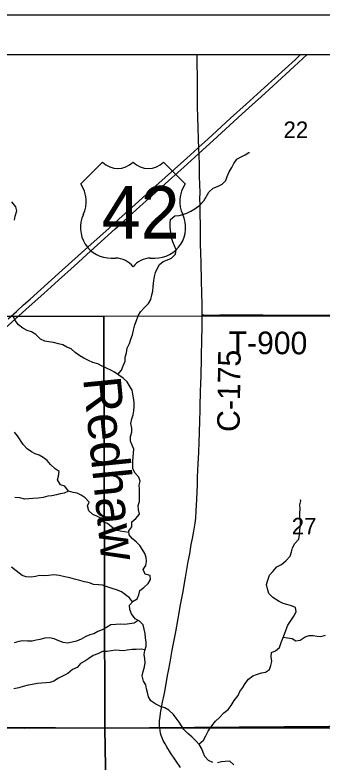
# Model space of a CAD drawing. Extents: x 0 to 34, y 0 to 22.
# Drawn here: x 14.264 to 15.039, y 14.196 to 16.078 of the extents above; entities that cross this region are included whole.
import ezdxf

# ---------------------------------------------------------------- set-up
doc = ezdxf.new("R2010")
doc.units = 0
for name, color, linetype in [('GM_X_County_Road', 7, 'Continuous'), ('GM_X_County_Road_Text', 7, 'Continuous'), ('GM_X_Minor_River', 7, 'Continuous'), ('GM_X_Minor_River_Text', 7, 'Continuous'), ('GM_X_Section', 7, 'Continuous'), ('GM_X_Section_Text', 7, 'Continuous'), ('GM_X_State_Route', 7, 'Continuous'), ('GM_X_Township_Road', 7, 'Continuous'), ('GM_X_Township_Road_Text', 7, 'Continuous'), ('GM_X_US_Location', 7, 'Continuous'), ('GM_X_US_Route', 7, 'Continuous'), ('GM_X_US_Shield', 7, 'Continuous'), ('SH_Data', 7, 'Continuous')]:
    doc.layers.add(name, color=color, linetype=linetype)

msp = doc.modelspace()

# ---------------------------------------------------------------- linework, layer by layer
at = {"layer": 'GM_X_County_Road'}
for points in [[(14.7287, 15.7292), (14.7285, 15.7359), (14.7281, 15.7443), (14.7274, 15.7607), (14.7262, 15.7973), (14.7256, 15.8164), (14.725, 15.8507), (14.7249, 15.8727), (14.7249, 15.9161), (14.7243, 15.9607), (14.7239, 15.9775)], [(14.7364, 15.3221), (14.7364, 15.3261), (14.7363, 15.3478), (14.7357, 15.3789), (14.7352, 15.4069), (14.7338, 15.4549), (14.7331, 15.4765), (14.7327, 15.5012), (14.7322, 15.5498), (14.7319, 15.5743), (14.7314, 15.5989), (14.731, 15.6143), (14.7311, 15.6304), (14.7302, 15.6707), (14.7297, 15.6956), (14.7287, 15.7292)], [(14.6297, 14.2821), (14.6292, 14.2856), (14.6289, 14.2916), (14.6293, 14.3006), (14.6302, 14.3098), (14.6316, 14.3191), (14.6368, 14.3466), (14.6404, 14.3649), (14.6438, 14.3832), (14.6494, 14.4137), (14.6517, 14.4259), (14.6556, 14.4478), (14.6612, 14.4781), (14.6698, 14.5239), (14.676, 14.5578), (14.6821, 14.5916), (14.6876, 14.6212), (14.6945, 14.661), (14.7016, 14.701), (14.705, 14.7202), (14.7091, 14.7438), (14.712, 14.7591), (14.7152, 14.7774), (14.7187, 14.798), (14.7202, 14.8102), (14.7217, 14.8287), (14.7229, 14.8574), (14.7244, 14.8947), (14.725, 14.9134), (14.7267, 14.9468), (14.7281, 14.9757), (14.7289, 15.0022), (14.7296, 15.0252), (14.7304, 15.056), (14.7311, 15.0813), (14.7317, 15.1026), (14.7323, 15.1187), (14.7327, 15.1321), (14.7333, 15.1468), (14.7341, 15.1708), (14.7344, 15.1832), (14.7347, 15.1987), (14.7349, 15.2205), (14.7357, 15.2578), (14.7362, 15.2919), (14.7364, 15.3221)], [(14.6816, 14.1823), (14.6568, 14.2195), (14.6476, 14.234), (14.6429, 14.2417), (14.6384, 14.2502), (14.6356, 14.2567), (14.6333, 14.2631), (14.6317, 14.2691), (14.6303, 14.2753), (14.6297, 14.2821)]]:
    msp.add_lwpolyline(points, dxfattribs=at)
at = {"layer": 'GM_X_Minor_River'}
for points in [[(14.5239, 15.1719), (14.5327, 15.1827), (14.5374, 15.1936), (14.542, 15.2053), (14.5425, 15.2159), (14.5456, 15.2265), (14.5472, 15.2383), (14.5534, 15.2504), (14.5565, 15.261), (14.5604, 15.2715), (14.5635, 15.284), (14.5667, 15.2973), (14.5709, 15.3082), (14.5748, 15.32), (14.5806, 15.3302), (14.5901, 15.3395), (14.6008, 15.3512), (14.607, 15.361), (14.6093, 15.3724), (14.6117, 15.3822), (14.6133, 15.394), (14.6142, 15.4084), (14.6162, 15.4186), (14.6189, 15.4288), (14.6235, 15.4394), (14.6285, 15.4492), (14.6384, 15.4563), (14.6491, 15.4611), (14.659, 15.4652), (14.6689, 15.475), (14.6709, 15.4856), (14.6668, 15.4962), (14.6623, 15.5062), (14.6587, 15.5187), (14.6572, 15.5297), (14.6558, 15.5419), (14.6555, 15.5529), (14.6564, 15.5624), (14.6678, 15.5714), (14.6781, 15.5724), (14.6879, 15.5746), (14.6978, 15.5786), (14.7081, 15.5835), (14.718, 15.5891), (14.7309, 15.5988), (14.7405, 15.609), (14.7535, 15.6316), (14.7642, 15.641), (14.7752, 15.6458), (14.787, 15.651), (14.7962, 15.6608), (14.7993, 15.6706), (14.8043, 15.6827), (14.8112, 15.6936), (14.8166, 15.7038), (14.8239, 15.7144), (14.8346, 15.72), (14.8448, 15.7252), (14.8544, 15.7315), (14.8559, 15.7315)], [(14.2629, 15.5605), (14.2649, 15.5707), (14.2688, 15.5843), (14.2666, 15.5946), (14.2561, 15.6065)], [(14.3395, 15.2562), (14.3285, 15.2609), (14.3165, 15.2728), (14.3056, 15.2793), (14.295, 15.2825), (14.2837, 15.2886), (14.2736, 15.2971), (14.2649, 15.3082), (14.2594, 15.3189)], [(14.6425, 14.3324), (14.6316, 14.3356), (14.6195, 14.3414), (14.6074, 14.3502), (14.6011, 14.3602), (14.5982, 14.3712), (14.5963, 14.3807), (14.5945, 14.3906), (14.5886, 14.4001), (14.5853, 14.4131), (14.5876, 14.4244), (14.5911, 14.4354), (14.5924, 14.4464), (14.5917, 14.4559), (14.5899, 14.4669), (14.5919, 14.4767), (14.595, 14.4877), (14.5951, 14.4976), (14.5936, 14.5086), (14.5926, 14.5196), (14.5904, 14.5303), (14.5875, 14.5413), (14.5781, 14.5509), (14.5679, 14.557), (14.5582, 14.5693), (14.5537, 14.5799), (14.5531, 14.5913), (14.5626, 14.6015), (14.5729, 14.6067), (14.5764, 14.6173), (14.5795, 14.6279), (14.589, 14.6358), (14.6001, 14.6455), (14.6063, 14.6561), (14.6056, 14.6656), (14.5927, 14.6695), (14.5879, 14.6809), (14.5941, 14.6911), (14.5957, 14.7013), (14.5954, 14.7112), (14.5917, 14.7215), (14.5853, 14.7318), (14.579, 14.7413), (14.5703, 14.7509), (14.5598, 14.7586), (14.5523, 14.7681), (14.5516, 14.778), (14.5589, 14.7886), (14.559, 14.8011), (14.5693, 14.8097), (14.5785, 14.8206), (14.5763, 14.8324), (14.5753, 14.8419), (14.5784, 14.8521), (14.5788, 14.862), (14.5782, 14.8734), (14.5783, 14.8832), (14.5776, 14.8931), (14.58, 14.9033), (14.577, 14.9132), (14.5676, 14.9236), (14.5617, 14.9342), (14.5618, 14.9547), (14.5623, 14.9642), (14.5631, 14.9748), (14.564, 14.9843), (14.5599, 14.9938), (14.5558, 15.0045), (14.5555, 15.0155), (14.559, 15.0268), (14.5588, 15.0371), (14.5562, 15.0489), (14.559, 15.0602), (14.5624, 15.0704), (14.5644, 15.0803), (14.5649, 15.0913), (14.565, 15.1011), (14.5636, 15.1133), (14.5618, 15.1228), (14.5596, 15.1323), (14.5528, 15.1438), (14.5472, 15.1537), (14.5375, 15.1629), (14.5262, 15.1702), (14.5157, 15.1783), (14.5058, 15.1833), (14.4949, 15.188), (14.4843, 15.193), (14.4734, 15.1988), (14.461, 15.2023), (14.45, 15.2074), (14.4383, 15.2128), (14.4282, 15.2193), (14.4161, 15.2278), (14.406, 15.237), (14.395, 15.2409), (14.3848, 15.2467), (14.3743, 15.2491), (14.3618, 15.2522), (14.3497, 15.2539), (14.3395, 15.2562)], [(14.5519, 14.7741), (14.5406, 14.7759), (14.5293, 14.7771), (14.5191, 14.7802), (14.5078, 14.7883), (14.498, 14.7964), (14.4882, 14.8003), (14.4807, 14.8098), (14.4705, 14.8152), (14.4603, 14.8195), (14.4506, 14.8283), (14.4476, 14.8409), (14.4511, 14.8507), (14.4414, 14.861), (14.4312, 14.8684), (14.4214, 14.873), (14.4108, 14.8746), (14.3991, 14.8785), (14.3898, 14.8904), (14.3792, 14.8943), (14.3713, 14.9065), (14.3741, 14.9163), (14.3757, 14.9277), (14.3655, 14.9346), (14.3539, 14.9454), (14.3456, 14.9553), (14.3358, 14.9634), (14.3257, 14.9688), (14.3155, 14.9723), (14.3057, 14.9773), (14.2948, 14.985), (14.285, 14.9957), (14.2708, 15.0175), (14.2633, 15.0271)], [(14.3991, 14.8785), (14.3888, 14.8729), (14.3786, 14.8711), (14.3691, 14.869), (14.357, 14.8664), (14.3468, 14.8654), (14.335, 14.8625), (14.3225, 14.8607), (14.3092, 14.8597), (14.299, 14.8586), (14.2888, 14.8584), (14.2763, 14.8611), (14.2638, 14.8624)], [(14.7284, 14.241), (14.7403, 14.2514), (14.7457, 14.2624), (14.7514, 14.2741), (14.7606, 14.2873), (14.7702, 14.2993), (14.7805, 14.308), (14.7916, 14.3196), (14.8019, 14.3282), (14.8095, 14.3384), (14.8176, 14.3512), (14.8276, 14.3633), (14.8318, 14.3739), (14.8391, 14.3837), (14.8449, 14.3935), (14.8533, 14.4044), (14.864, 14.413), (14.8735, 14.4167), (14.886, 14.4204), (14.8962, 14.4222), (14.9061, 14.4293), (14.91, 14.4395), (14.9124, 14.4493), (14.9109, 14.4611), (14.9114, 14.4721), (14.9217, 14.4758), (14.9316, 14.4848), (14.9355, 14.4969), (14.944, 14.5181), (14.9483, 14.5302), (14.9525, 14.5404), (14.9594, 14.551), (14.9675, 14.563), (14.974, 14.5747), (14.9718, 14.5854), (14.9616, 14.5893), (14.9503, 14.5928), (14.9405, 14.5952), (14.9307, 14.6002), (14.9149, 14.6102), (14.9051, 14.6205), (14.9014, 14.632), (14.8989, 14.6434), (14.9024, 14.6543), (14.9066, 14.6664), (14.9147, 14.6762), (14.925, 14.6875), (14.9368, 14.6931), (14.9475, 14.7028), (14.9589, 14.7149), (14.9616, 14.7251), (14.9644, 14.7357), (14.9702, 14.7463), (14.9801, 14.7572), (14.9825, 14.7693), (14.9826, 14.7807), (14.9849, 14.7905), (14.9843, 14.8026), (14.9832, 14.8125), (14.9833, 14.8231), (14.9838, 14.8334), (14.9831, 14.8436), (14.9858, 14.8535), (14.9847, 14.8561)], [(14.5607, 14.5995), (14.5532, 14.6099), (14.5434, 14.6168), (14.5333, 14.6249), (14.5227, 14.6292), (14.5095, 14.6331), (14.4993, 14.6366), (14.4853, 14.6413), (14.4747, 14.6422), (14.4626, 14.6431), (14.4521, 14.6473), (14.44, 14.6497), (14.4275, 14.6536), (14.4147, 14.6568), (14.4029, 14.6603), (14.3901, 14.6624), (14.3761, 14.6655), (14.3621, 14.6672), (14.3485, 14.6662), (14.3371, 14.6648), (14.3265, 14.666), (14.3159, 14.6631), (14.3049, 14.662), (14.2928, 14.6622), (14.2822, 14.6657), (14.2675, 14.6776), (14.2559, 14.6864)], [(14.575, 14.5528), (14.5648, 14.5461), (14.553, 14.5439), (14.5413, 14.5425), (14.5296, 14.543), (14.519, 14.5423), (14.5057, 14.5417), (14.495, 14.535), (14.484, 14.5286), (14.4737, 14.5249), (14.4631, 14.519), (14.4532, 14.5168), (14.4433, 14.512), (14.4315, 14.5056), (14.4194, 14.5008), (14.4084, 14.4975), (14.3966, 14.495), (14.3857, 14.497), (14.3747, 14.5016), (14.363, 14.5063), (14.3513, 14.5091), (14.3396, 14.508), (14.327, 14.5044), (14.3175, 14.5026), (14.3077, 14.5008), (14.2963, 14.5005), (14.2838, 14.501), (14.2743, 14.4992), (14.2626, 14.4959)], [(14.941, 14.5108), (14.9519, 14.5085), (14.9632, 14.5073), (14.973, 14.5015), (14.984, 14.5033), (14.9966, 14.5111), (15.0064, 14.5145), (15.0163, 14.5144), (15.0265, 14.5127), (15.0363, 14.5123), (15.0473, 14.5152)], [(14.5923, 14.4783), (14.5824, 14.4799), (14.5699, 14.4796), (14.5601, 14.4793), (14.5472, 14.4779), (14.5377, 14.4761), (14.5279, 14.4766), (14.518, 14.4778), (14.5067, 14.4761), (14.4972, 14.4743), (14.4854, 14.4747), (14.4736, 14.4688), (14.4615, 14.4644), (14.4504, 14.4565), (14.4402, 14.4498), (14.4299, 14.4442), (14.4215, 14.434), (14.4097, 14.4292), (14.3975, 14.4194), (14.3846, 14.4124), (14.3743, 14.4071), (14.3625, 14.4001), (14.3519, 14.3964), (14.342, 14.3953), (14.3314, 14.395), (14.3212, 14.394), (14.3079, 14.3915), (14.2973, 14.3893), (14.2847, 14.386), (14.2737, 14.3827), (14.2616, 14.3805)], [(14.7636, 14.1951), (14.7527, 14.2001), (14.7433, 14.2097), (14.7392, 14.22), (14.7355, 14.2295), (14.7299, 14.2394), (14.7202, 14.2497), (14.7108, 14.2593), (14.7007, 14.2681), (14.6901, 14.2777), (14.6845, 14.2873), (14.6782, 14.2968), (14.6711, 14.3064), (14.6643, 14.3159), (14.6523, 14.327), (14.6425, 14.3324)], [(14.8166, 14.1892), (14.8065, 14.198), (14.7947, 14.1978), (14.7852, 14.1967), (14.775, 14.1938)]]:
    msp.add_lwpolyline(points, dxfattribs=at)
at = {"layer": 'GM_X_Section'}
for points in [[(14.4882, 15.3186), (14.4911, 14.2816), (13.9911, 14.2848), (13.6079, 14.3123), (13.4623, 14.3061), (13.4573, 15.3188)], [(15.4934, 15.3198), (15.5087, 14.2889), (14.4911, 14.2816), (14.4882, 15.3186)], [(14.4911, 14.2816), (14.5077, 13.2997), (13.5746, 13.3006), (13.5034, 13.3022), (13.4623, 14.3061), (13.6079, 14.3123), (13.9911, 14.2848)], [(15.5087, 14.2889), (15.5148, 13.3016), (14.5623, 13.2983), (14.5077, 13.2997), (14.4911, 14.2816)]]:
    msp.add_lwpolyline(points, close=True, dxfattribs=at)
at = {"layer": 'GM_X_State_Route'}
msp.add_lwpolyline([(14.2231, 14.282), (14.2886, 14.2816), (14.3465, 14.2821), (14.4338, 14.2822), (14.4823, 14.2825), (14.5351, 14.2824), (14.5724, 14.2824), (14.6137, 14.2819), (14.6297, 14.2821), (14.6823, 14.2822), (14.7484, 14.2819), (14.7925, 14.2819), (14.8365, 14.2818), (14.8893, 14.282), (14.9483, 14.2821), (14.9949, 14.282), (15.0321, 14.2819), (15.0694, 14.282)], dxfattribs=at)
at = {"layer": 'GM_X_Township_Road'}
msp.add_lwpolyline([(14.7364, 15.3221), (14.7406, 15.322), (14.7561, 15.3218), (14.781, 15.322), (14.8338, 15.3222), (14.8587, 15.3222), (14.8898, 15.3219), (14.9333, 15.3218), (14.9644, 15.3216), (15.0546, 15.3215), (15.1012, 15.3213), (15.151, 15.3212), (15.1914, 15.321), (15.2349, 15.321), (15.2359, 15.321)], dxfattribs=at)
at = {"layer": 'GM_X_US_Route'}
for points in [[(14.2213, 15.2724), (14.2653, 15.3118), (14.2999, 15.343), (14.3369, 15.3763), (14.3737, 15.4098), (14.4132, 15.4447), (14.4453, 15.4742), (14.517, 15.5386), (14.5377, 15.5573), (14.5608, 15.5781), (14.5794, 15.5947), (14.6093, 15.6219), (14.6603, 15.6674), (14.6904, 15.6944), (14.7272, 15.7279), (14.7287, 15.7292), (14.7641, 15.7612), (14.8375, 15.8283), (14.8628, 15.8513), (14.886, 15.872), (14.9157, 15.8994), (14.9688, 15.9473), (15.0018, 15.9775)], [(14.2472, 15.3118), (14.2679, 15.3307), (14.2862, 15.3474), (14.3025, 15.3619), (14.3836, 15.4344), (14.4482, 15.4927), (14.5015, 15.5403), (14.5267, 15.5633), (14.5497, 15.5842), (14.6123, 15.6402), (14.6979, 15.717), (14.7255, 15.742), (14.7281, 15.7443), (14.7509, 15.7649), (14.7739, 15.7859), (14.8083, 15.8173), (14.8476, 15.8527), (14.8936, 15.8945), (14.9719, 15.9655), (14.985, 15.9775)]]:
    msp.add_lwpolyline(points, dxfattribs=at)
at = {"layer": 'GM_X_US_Shield'}
for p, q in [((14.4853, 15.7067), (14.4303, 15.6518)), ((14.694, 15.6518), (14.6391, 15.7067)), ((14.5072, 15.465), (14.5182, 15.465)), ((14.6061, 15.465), (14.6171, 15.465))]:
    msp.add_line(p, q, dxfattribs=at)
for centre, radius, start, end in [((14.5237, 15.7459), 0.0549, 225.573, 314.427), ((14.6006, 15.7459), 0.0549, 225.573, 314.427), ((14.3673, 15.6077), 0.0769, 334.5471, 35.0009), ((14.757, 15.6077), 0.0769, 144.9991, 205.4529), ((14.5064, 15.5419), 0.0769, 154.8319, 270.6383), ((14.618, 15.5419), 0.0769, 269.3617, 25.1681), ((14.5182, 15.4101), 0.0549, 36.8699, 90), ((14.6061, 15.4101), 0.0549, 90, 143.1301)]:
    msp.add_arc(centre, radius, start, end, dxfattribs=at)
at = {"layer": 'SH_Data'}
for p, q in [((9.0079, 16.0775), (16.0079, 16.0775)), ((9.1079, 15.9775), (15.9079, 15.9775))]:
    msp.add_line(p, q, dxfattribs=at)

# ---------------------------------------------------------------- texts
at = {"layer": 'GM_X_County_Road_Text'}
msp.add_text('C-175', height=0.05682, rotation=89.1754, dxfattribs=at).set_placement((14.8309, 15.027))
at = {"layer": 'GM_X_Minor_River_Text'}
msp.add_text('Redhaw', height=0.09473, rotation=275.7262, dxfattribs=at).set_placement((14.4361, 15.162))
at = {"layer": 'GM_X_Section_Text'}
for s, p in [('22', (14.9418, 15.7673)), ('27', (14.9626, 14.7691))]:
    msp.add_text(s, height=0.04186, rotation=0, dxfattribs=at).set_placement(p)
at = {"layer": 'GM_X_Township_Road_Text'}
msp.add_text('T-900', height=0.05682, rotation=359.7177, dxfattribs=at).set_placement((14.8032, 15.2237))
at = {"layer": 'GM_X_US_Location'}
for s in ['0', '/']:
    msp.add_text(s, height=0.000189, dxfattribs=at).set_placement((14.5621, 15.5793))
msp.add_text('42', height=0.000189, rotation=0, dxfattribs=at).set_placement((14.523, 15.5401))
at = {"layer": 'GM_X_US_Shield'}
msp.add_text('42', height=0.13184, dxfattribs=at).set_placement((14.4834, 15.5145))

doc.saveas('drawing.dxf')
